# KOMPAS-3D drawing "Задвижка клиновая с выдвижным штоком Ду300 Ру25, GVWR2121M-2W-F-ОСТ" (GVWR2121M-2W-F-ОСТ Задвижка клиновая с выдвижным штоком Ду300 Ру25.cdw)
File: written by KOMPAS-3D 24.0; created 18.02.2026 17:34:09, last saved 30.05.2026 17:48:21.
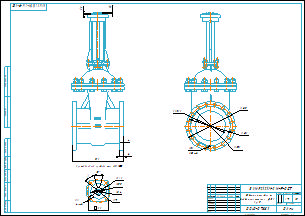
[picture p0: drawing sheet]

Document properties: Автор: R2D2; Форматы листов документа: A2; Полное имя файла: GVWR2121M-2W-F-ОСТ Задвижка клиновая с выдвижным штоком Ду300 Ру25.m3d; Масса: 270; Наименование: Задвижка клиновая с выдвижным штоком Ду300 Ру25; Количество листов документа: 1; Примечание: D040-07881

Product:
- Part/product: Задвижка клиновая с выдвижным штоком Ду300 Ру25  | designation GVWR2121M-2W-F-ОСТ
    Масса: 270
    Раздел спецификации: Прочие изделия
    Примечание: D040-07881

Views: Вид 1, Спереди, Проекционный вид 3
Referenced files in E:\Работа\Зайцев\GVWR2434M-2W-F-ОСТ Задвижка клиновая с выдвижным штоком DN.ru Ду50-300 Ру25\исходные материалы\DN300\DN300\: GVWR2434M-2W-F-ОСТ Задвижка клиновая с выдвижным штоком Ду300 Ру25.m3d
Referenced files in E:\Работа\Зайцев\GVWR2121M-2W-F-ОСТ Задвижка клиновая 30с964нж DN.ru Ду50-300 Ру25\исходные материалы\DN300\DN300\: GVWR2121M-2W-F-ОСТ Задвижка клиновая с выдвижным штоком Ду300 Ру25.m3d
Referenced files in E:\Работа\Зайцев\Для компаса\: чертеж DN.ru А3.cdt
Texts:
  GVWR2121M-2W-F-ОСТ
  Присоединение привода тип АК (В)
  чертеж DN.ru А3.cdt
  Задвижка клиновая с
  выдвижным штоком Ду300
  Ру25
  Задвижка клиновая с выдвижным штоком Ду300 Ру25
  GVWR2121M-2W-F-ОСТ Задвижка клиновая с выдвижным штоком Ду300 Ру25
Dimensions and other numbers on the sheet: 0; 3; 2; 4; 500; 40; 10; 200; 220; 155; 84; 70; 22; 4 отв.; 1:5; 1; 270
